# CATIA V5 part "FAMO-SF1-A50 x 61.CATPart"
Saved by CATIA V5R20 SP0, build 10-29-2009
Part number: FAMO-SF1-A50 x 61
Definition: NONE
Nomenclature: FAMO-SF1-A50 x 61
Source: Unknown
Description: FAMO-SF1-A50 x 61
Bounding box of the stored display mesh (mm): x -13 to 48, y -39.5 to 39.5, z -39.5 to 39.5
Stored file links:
  C:\Users\Utente\Desktop\IO LAVORO\3D X SITO CF\X SITO\FAMO\FAMO-SF1-A50 x 61.CATPart
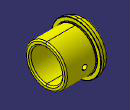
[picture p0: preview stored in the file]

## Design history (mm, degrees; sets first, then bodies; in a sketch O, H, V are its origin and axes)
Body1 "FAMO-SF1-A50 x 61" (main body)
  Solid1: solid without history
